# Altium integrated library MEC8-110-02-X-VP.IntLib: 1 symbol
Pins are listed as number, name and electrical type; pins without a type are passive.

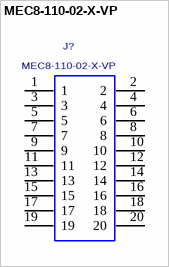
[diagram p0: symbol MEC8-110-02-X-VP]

## MEC8-110-02-X-VP
designator J?
0.80 MM PRESS FIT MINI-EDGE CARD ASSEMBLY.; MANUFACTURER: SAMTEC
footprint MEC8-110-02-X-VP
pins: 1, 2, 3, 4, 5, 6, 7, 8, 9, 10, 11, 12, 13, 14, 15, 16, 17, 18, 19, 20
